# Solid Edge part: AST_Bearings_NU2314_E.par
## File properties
Author: Nimesh.N
Template: iso metric part.par
Last saved by: Nimesh.N
Revision: 22
Application: Solid Edge
Density: 7800.000 kg/m^3
Accuracy: 0.990
Username: Nimesh.N
Material: Steel - Alloyed:1.7016 , 17Cr3
Face Style: Steel
Fill Style: ANSI32(Steel)
Grouping: Steel\Steel - Alloyed (Cr)
LibraryName: Materials-DIN
Coef. of Thermal Exp: 1.1e-05
Thermal Conductivity: 14.0
Specific Heat: 440.0
Modulus of Elasticity: 210000003072.0
Poisson's Ratio: 0.28
Yield Stress: 420000000.0
Ultimate Stress: 550000000.0
Elongation: 0.0
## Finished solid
Body 1: solid body, 124 faces, 360 edges, 212 vertices.
  Faces by surface: plane 82, cylinder 38, torus 4
  Edges by curve: circle 294, line 66
Body 2: solid body, 14 faces, 28 edges, 16 vertices.
  Faces by surface: cylinder 6, torus 4, cone 2, plane 2
  Edges by curve: circle 20, line 8
Bounding box of the edges (mm; curved faces can reach further): 51.000 x 150.000 x 150.000, from (-25.5, -75, -75) to (25.5, 75, 75).
Cylindrical faces by radius (mm): R10 x26, R35 x2, R45 x4, R54.25 x2, R57.25 x2, R62 x4, R65 x2, R75 x2
Conical faces (half-angle, radius in mm at the cone's reference point): 20 deg R43.9823 x2
Toroidal faces (ring radius, tube radius in mm): R37.55 r2.55 x4, R72.45 r2.55 x4
Planar faces by outward normal: +x 42, -x 42
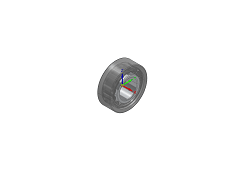
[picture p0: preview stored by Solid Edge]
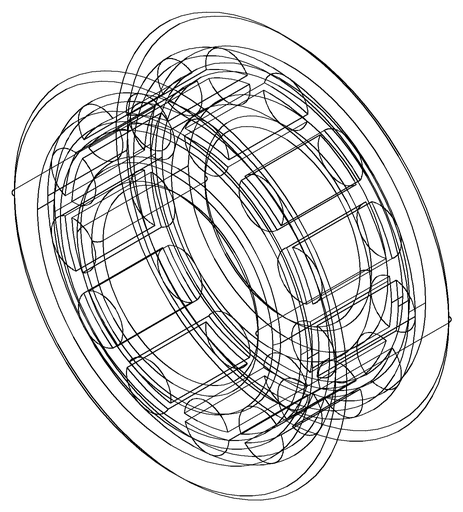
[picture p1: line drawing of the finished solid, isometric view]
